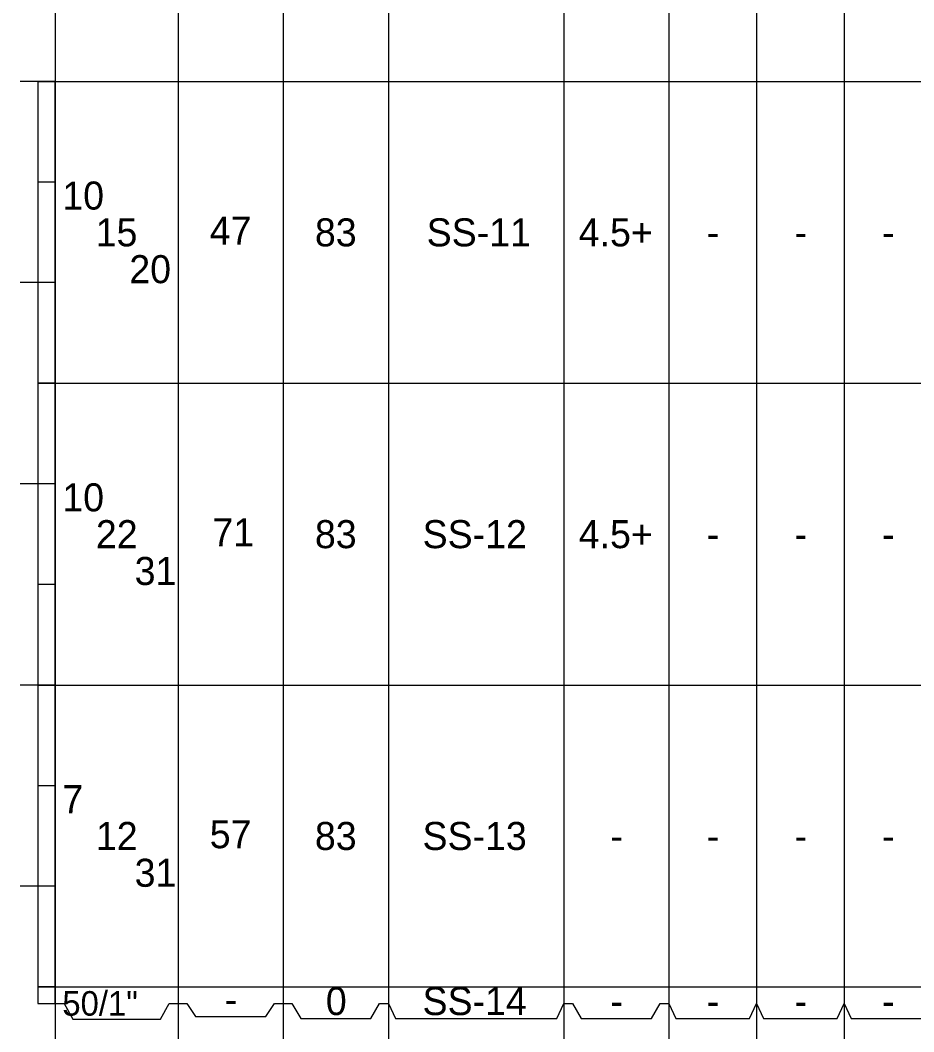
# Model space of a CAD drawing. Extents: x 0 to 0.83, y -0.65 to 1.27.
# Drawn here: x 0.4042 to 0.6165, y 0.2046 to 0.4451 of the extents above; entities that cross this region are included whole.
import ezdxf

# ---------------------------------------------------------------- set-up
doc = ezdxf.new("R2010")
doc.units = 0

msp = doc.modelspace()

# ---------------------------------------------------------------- linework, layer by layer
for points in [[(0.4125, 1.22083), (0.4125, -0.64575)], [(0.4125, 1.22083), (0.4125, -0.64575)], [(0.44167, 1.22083), (0.44167, -0.64575)], [(0.46667, 1.22083), (0.46667, -0.64575)], [(0.49167, 1.22083), (0.49167, -0.64575)], [(0.53333, 1.22083), (0.53333, -0.64575)], [(0.55833, 1.22083), (0.55833, -0.64575)], [(0.57917, 1.20833), (0.57917, -0.64575)], [(0.6, 1.20833), (0.6, -0.64575)], [(0.4125, 0.4305), (0.40417, 0.4305)], [(0.40833, 0.4305), (0.40833, 0.35875)], [(0.40833, 0.4305), (0.4125, 0.4305)], [(0.4125, 0.4305), (0.40833, 0.4305)], [(0.4125, 0.4305), (0.44167, 0.4305)], [(0.44167, 0.4305), (0.46667, 0.4305)], [(0.46667, 0.4305), (0.49167, 0.4305)], [(0.49167, 0.4305), (0.53333, 0.4305)], [(0.53333, 0.4305), (0.55833, 0.4305)], [(0.55833, 0.4305), (0.57917, 0.4305)], [(0.57917, 0.4305), (0.6, 0.4305)], [(0.6, 0.4305), (0.62083, 0.4305)], [(0.4125, 0.40658), (0.40833, 0.40658)], [(0.4125, 0.38267), (0.40417, 0.38267)], [(0.4125, 0.38267), (0.40833, 0.38267)], [(0.40833, 0.35875), (0.4125, 0.35875)], [(0.40833, 0.35875), (0.40833, 0.287)], [(0.40833, 0.35875), (0.4125, 0.35875)], [(0.4125, 0.35875), (0.40833, 0.35875)], [(0.4125, 0.35875), (0.44167, 0.35875)], [(0.44167, 0.35875), (0.46667, 0.35875)], [(0.46667, 0.35875), (0.49167, 0.35875)], [(0.49167, 0.35875), (0.53333, 0.35875)], [(0.53333, 0.35875), (0.55833, 0.35875)], [(0.55833, 0.35875), (0.57917, 0.35875)], [(0.57917, 0.35875), (0.6, 0.35875)], [(0.6, 0.35875), (0.62083, 0.35875)], [(0.4125, 0.33483), (0.40417, 0.33483)], [(0.4125, 0.33483), (0.40833, 0.33483)], [(0.4125, 0.31092), (0.40833, 0.31092)], [(0.4125, 0.287), (0.40417, 0.287)], [(0.40833, 0.287), (0.4125, 0.287)], [(0.40833, 0.287), (0.40833, 0.21525)], [(0.40833, 0.287), (0.4125, 0.287)], [(0.4125, 0.287), (0.40833, 0.287)], [(0.4125, 0.287), (0.44167, 0.287)], [(0.44167, 0.287), (0.46667, 0.287)], [(0.46667, 0.287), (0.49167, 0.287)], [(0.49167, 0.287), (0.53333, 0.287)], [(0.53333, 0.287), (0.55833, 0.287)], [(0.55833, 0.287), (0.57917, 0.287)], [(0.57917, 0.287), (0.6, 0.287)], [(0.6, 0.287), (0.62083, 0.287)], [(0.4125, 0.26308), (0.40833, 0.26308)], [(0.4125, 0.23917), (0.40417, 0.23917)], [(0.4125, 0.23917), (0.40833, 0.23917)], [(0.40833, 0.21525), (0.4125, 0.21525)], [(0.40833, 0.21525), (0.40833, 0.21126)], [(0.40833, 0.21525), (0.4125, 0.21525)], [(0.4125, 0.21525), (0.40833, 0.21525)], [(0.4125, 0.21525), (0.44167, 0.21525)], [(0.44167, 0.21525), (0.46667, 0.21525)], [(0.46667, 0.21525), (0.49167, 0.21525)], [(0.49167, 0.21525), (0.53333, 0.21525)], [(0.53333, 0.21525), (0.55833, 0.21525)], [(0.55833, 0.21525), (0.57917, 0.21525)], [(0.57917, 0.21525), (0.6, 0.21525)], [(0.6, 0.21525), (0.62083, 0.21525)], [(0.40833, 0.21126), (0.4125, 0.21126)], [(0.4125, 0.21126), (0.41458, 0.21126), (0.41667, 0.20759), (0.4375, 0.20759), (0.43958, 0.21126), (0.44167, 0.21126)], [(0.44167, 0.21126), (0.44375, 0.21126), (0.44583, 0.20817), (0.4625, 0.20817), (0.46458, 0.21126), (0.46667, 0.21126)], [(0.46667, 0.21126), (0.46875, 0.21126), (0.47083, 0.20775), (0.4875, 0.20775), (0.48958, 0.21126), (0.49167, 0.21126)], [(0.49167, 0.21126), (0.49333, 0.20775), (0.53167, 0.20775), (0.53333, 0.21126)], [(0.53333, 0.21126), (0.53542, 0.21126), (0.5375, 0.20775), (0.55417, 0.20775), (0.55625, 0.21126), (0.55833, 0.21126)], [(0.55833, 0.21126), (0.56, 0.20775), (0.5775, 0.20775), (0.57917, 0.21126)], [(0.57917, 0.21126), (0.58083, 0.20775), (0.59833, 0.20775), (0.6, 0.21126)], [(0.6, 0.21126), (0.60167, 0.20775), (0.61917, 0.20775), (0.62083, 0.21126)]]:
    msp.add_lwpolyline(points)
for points in [[(0.40833, 0.35875), (0.4125, 0.35875), (0.4125, 0.4305), (0.40833, 0.4305)], [(0.40833, 0.287), (0.4125, 0.287), (0.4125, 0.35875), (0.40833, 0.35875)], [(0.40833, 0.21525), (0.4125, 0.21525), (0.4125, 0.287), (0.40833, 0.287)], [(0.40833, 0.21126), (0.4125, 0.21126), (0.4125, 0.21525), (0.40833, 0.21525)]]:
    msp.add_lwpolyline(points, close=True)

# ---------------------------------------------------------------- texts
for s, height, p in [('10', 0.006667, (0.41417, 0.40004)), ('15', 0.006667, (0.42209, 0.39129)), ('47', 0.006667, (0.4492, 0.39171)), ('83', 0.006667, (0.4742, 0.39129)), ('SS-11', 0.006667, (0.50076, 0.39129)), ('4.5+', 0.006667, (0.5369, 0.39129)), ('-', 0.00667, (0.56734, 0.39129)), ('-', 0.00667, (0.58818, 0.39129)), ('-', 0.00667, (0.60901, 0.39129)), ('20', 0.006667, (0.43009, 0.38254)), ('10', 0.006667, (0.41417, 0.32829)), ('22', 0.006667, (0.42215, 0.31954)), ('71', 0.006667, (0.44984, 0.31996)), ('83', 0.006667, (0.4742, 0.31954)), ('SS-12', 0.006667, (0.4998, 0.31954)), ('4.5+', 0.006667, (0.5369, 0.31954)), ('-', 0.00667, (0.56734, 0.31954)), ('-', 0.00667, (0.58818, 0.31954)), ('-', 0.00667, (0.60901, 0.31954)), ('31', 0.006667, (0.43136, 0.31079)), ('7', 0.00667, (0.41417, 0.25654)), ('12', 0.006667, (0.42215, 0.24779)), ('57', 0.006667, (0.4492, 0.24821)), ('83', 0.006667, (0.4742, 0.24779)), ('SS-13', 0.006667, (0.49977, 0.24779)), ('-', 0.00667, (0.54443, 0.24779)), ('-', 0.00667, (0.56734, 0.24779)), ('-', 0.00667, (0.58818, 0.24779)), ('-', 0.00667, (0.60901, 0.24779)), ('31', 0.006667, (0.43136, 0.23904)), ('50/1"', 0.005833, (0.41417, 0.2084)), ('0', 0.00667, (0.4768, 0.20854)), ('SS-14', 0.006667, (0.49978, 0.20854)), ('-', 0.00667, (0.45276, 0.20896)), ('-', 0.00667, (0.54443, 0.20854)), ('-', 0.00667, (0.56734, 0.20854)), ('-', 0.00667, (0.58818, 0.20854)), ('-', 0.00667, (0.60901, 0.20854))]:
    msp.add_text(s, height=height).set_placement(p)

doc.saveas('drawing.dxf')
